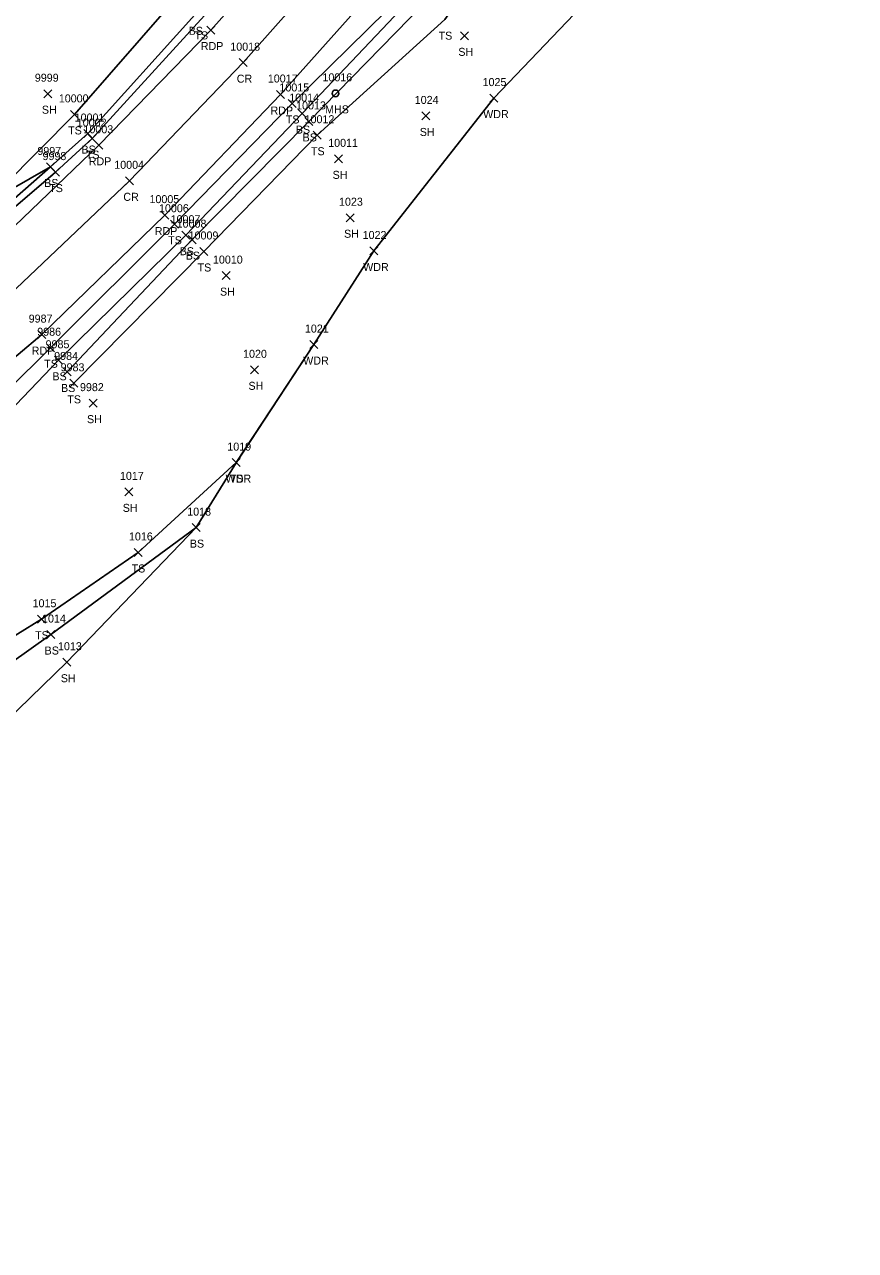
# Model space of a CAD drawing. Extents: x 1651685 to 1653558, y 889533 to 891085.
# Drawn here: x 1652499.4 to 1652707.1, y 889769.1 to 890075.4 of the extents above; entities that cross this region are included whole.
import ezdxf

# ---------------------------------------------------------------- set-up
doc = ezdxf.new("R2010")
doc.units = 0
for name, color, linetype in [('L_A', 7, 'Continuous'), ('L_I', 7, 'Continuous'), ('L_TIC', 7, 'Continuous'), ('LAWA', 7, 'Continuous'), ('LELB', 7, 'Continuous'), ('LSOGP', 7, 'Continuous'), ('P_A', 7, 'Continuous'), ('P_I', 7, 'Continuous'), ('P_TIC', 7, 'Continuous'), ('PET', 7, 'Continuous'), ('PRC', 7, 'Continuous'), ('U_A', 7, 'Continuous'), ('U_I', 7, 'Continuous'), ('USMH', 7, 'Continuous')]:
    doc.layers.add(name, color=color, linetype=linetype)

msp = doc.modelspace()

# ---------------------------------------------------------------- linework, layer by layer
at = {"layer": 'L_TIC'}
for points in [[(1652608.31, 890071.58), (1652610.31, 890073.58)], [(1652610.31, 890071.58), (1652608.31, 890073.58)], [(1652504.25, 890057.12), (1652506.25, 890059.12)], [(1652506.25, 890057.12), (1652504.25, 890059.12)], [(1652615.65, 890056.03), (1652617.65, 890058.03)], [(1652617.65, 890056.03), (1652615.65, 890058.03)], [(1652565.28, 890054.69), (1652567.28, 890056.69)], [(1652567.28, 890054.69), (1652565.28, 890056.69)], [(1652567.75, 890052.15), (1652569.75, 890054.15)], [(1652569.75, 890052.15), (1652567.75, 890054.15)], [(1652510.88, 890051.95), (1652512.88, 890053.95)], [(1652512.88, 890051.95), (1652510.88, 890053.95)], [(1652569.45, 890050.2), (1652571.45, 890052.2)], [(1652571.45, 890050.2), (1652569.45, 890052.2)], [(1652598.68, 890051.57), (1652600.68, 890053.57)], [(1652600.68, 890051.57), (1652598.68, 890053.57)], [(1652514.19, 890047.17), (1652516.19, 890049.17)], [(1652516.19, 890047.17), (1652514.19, 890049.17)], [(1652571.57, 890046.75), (1652573.57, 890048.75)], [(1652573.57, 890046.75), (1652571.57, 890048.75)], [(1652515.29, 890045.9), (1652517.29, 890047.9)], [(1652517.29, 890045.9), (1652515.29, 890047.9)], [(1652576.9, 890040.85), (1652578.9, 890042.85)], [(1652578.9, 890040.85), (1652576.9, 890042.85)], [(1652504.87, 890038.82), (1652506.87, 890040.82)], [(1652506.87, 890038.82), (1652504.87, 890040.82)], [(1652504.87, 890038.82), (1652506.87, 890040.82)], [(1652506.87, 890038.82), (1652504.87, 890040.82)], [(1652506.16, 890037.54), (1652508.16, 890039.54)], [(1652508.16, 890037.54), (1652506.16, 890039.54)], [(1652535.9, 890024.51), (1652537.9, 890026.51)], [(1652537.9, 890024.51), (1652535.9, 890026.51)], [(1652579.76, 890026.14), (1652581.76, 890028.14)], [(1652581.76, 890026.14), (1652579.76, 890028.14)], [(1652538.73, 890021.77), (1652540.73, 890023.77)], [(1652540.73, 890021.77), (1652538.73, 890023.77)], [(1652540.26, 890020.66), (1652542.26, 890022.66)], [(1652542.26, 890020.66), (1652540.26, 890022.66)], [(1652543.24, 890017.71), (1652545.24, 890019.71)], [(1652545.24, 890017.71), (1652543.24, 890019.71)], [(1652585.67, 890017.83), (1652587.67, 890019.83)], [(1652587.67, 890017.83), (1652585.67, 890019.83)], [(1652548.76, 890011.68), (1652550.76, 890013.68)], [(1652550.76, 890011.68), (1652548.76, 890013.68)], [(1652570.67, 889994.45), (1652572.67, 889996.45)], [(1652572.67, 889994.45), (1652570.67, 889996.45)], [(1652504.9, 889993.66), (1652506.9, 889995.66)], [(1652506.9, 889993.66), (1652504.9, 889995.66)], [(1652506.93, 889990.53), (1652508.93, 889992.53)], [(1652508.93, 889990.53), (1652506.93, 889992.53)], [(1652555.88, 889988.15), (1652557.88, 889990.15)], [(1652557.88, 889988.15), (1652555.88, 889990.15)], [(1652509.07, 889987.61), (1652511.07, 889989.61)], [(1652511.07, 889987.61), (1652509.07, 889989.61)], [(1652510.69, 889984.78), (1652512.69, 889986.78)], [(1652512.69, 889984.78), (1652510.69, 889986.78)], [(1652515.52, 889979.82), (1652517.52, 889981.82)], [(1652517.52, 889979.82), (1652515.52, 889981.82)], [(1652551.29, 889964.96), (1652553.29, 889966.96)], [(1652553.29, 889964.96), (1652551.29, 889966.96)], [(1652551.29, 889964.96), (1652553.29, 889966.96)], [(1652553.29, 889964.96), (1652551.29, 889966.96)], [(1652524.46, 889957.66), (1652526.46, 889959.66)], [(1652526.46, 889957.66), (1652524.46, 889959.66)], [(1652541.27, 889948.72), (1652543.27, 889950.72)], [(1652543.27, 889948.72), (1652541.27, 889950.72)], [(1652526.76, 889942.52), (1652528.76, 889944.52)], [(1652528.76, 889942.52), (1652526.76, 889944.52)], [(1652502.63, 889925.84), (1652504.63, 889927.84)], [(1652504.63, 889925.84), (1652502.63, 889927.84)], [(1652504.98, 889922.02), (1652506.98, 889924.02)], [(1652506.98, 889922.02), (1652504.98, 889924.02)], [(1652508.97, 889915.1), (1652510.97, 889917.1)], [(1652510.97, 889915.1), (1652508.97, 889917.1)]]:
    msp.add_lwpolyline(points, dxfattribs=at)
at = {"layer": 'LAWA'}
msp.add_lwpolyline([(1652552.29, 889965.96), (1652571.67, 889995.45), (1652586.67, 890018.83), (1652616.65, 890057.03), (1652642.24, 890083.82), (1652665.45, 890109.51), (1652678.78, 890135.45), (1652680.4, 890163.12)], dxfattribs=at)
at = {"layer": 'LELB'}
for points in [[(1652293.22, 889915.66), (1652303.09, 889907.93), (1652317.35, 889908.79), (1652320.69, 889910.3), (1652331.92, 889916.22), (1652367.25, 889934.93), (1652401.81, 889955.3), (1652430.74, 889974.75), (1652457.46, 889995.31), (1652485.92, 890020.39), (1652507.16, 890038.54), (1652516.29, 890046.9), (1652543.45, 890076.69), (1652569.75, 890105.32), (1652598.99, 890142.55), (1652623.84, 890175.33), (1652642.78, 890202.62), (1652649.43, 890213.08), (1652650.34, 890219.8), (1652662.3, 890235.67), (1652673.05, 890250.91), (1652676.63, 890257.99), (1652674.28, 890264.42)], [(1652348.15, 889927.34), (1652366.56, 889935.99), (1652400.4, 889956.7), (1652430.05, 889976.64), (1652456.7, 889996.32), (1652485.07, 890021.64), (1652505.87, 890039.82), (1652515.19, 890048.17), (1652541.97, 890077.83), (1652568.76, 890106.07), (1652597.37, 890144.26), (1652620.77, 890177.54), (1652638.78, 890206.49), (1652647.21, 890219), (1652658.7, 890237.83), (1652668.92, 890254.32), (1652671.69, 890259.27)], [(1652059.96, 889769.15), (1652077.1, 889776.34), (1652118.69, 889793.55), (1652148.83, 889805.14), (1652195.57, 889824.7), (1652235.22, 889839.02), (1652273.17, 889851.71), (1652312.19, 889868.5), (1652346.46, 889887.35), (1652384.44, 889904.89), (1652418.63, 889927.64), (1652449.26, 889948.79), (1652484.18, 889973.18), (1652505.9, 889994.66), (1652536.9, 890025.51), (1652566.28, 890055.69), (1652594.63, 890083.58), (1652622.18, 890122.04), (1652650.06, 890154.47), (1652669.87, 890181.83), (1652676.09, 890189.41), (1652687.77, 890202.23), (1652700.09, 890224.17)], [(1652442.28, 889988.62), (1652454.4, 889999.19), (1652483.45, 890024.67), (1652494.27, 890035.14), (1652511.88, 890052.95), (1652537.3, 890082.09), (1652561.99, 890110.81), (1652590.74, 890149.47), (1652610.85, 890183.15), (1652631.18, 890211.95), (1652637.71, 890221.97)], [(1652510.07, 889988.61), (1652541.26, 890021.66), (1652570.45, 890051.2), (1652599.26, 890080.66), (1652627.52, 890117.73), (1652652.74, 890152.48), (1652673.77, 890178.69), (1652683.33, 890184.78), (1652690.8, 890198.36), (1652694.16, 890203.39)], [(1652425.64, 889918.85), (1652456.73, 889936.26), (1652476.98, 889952.39), (1652484.78, 889967.5), (1652507.93, 889991.53), (1652539.73, 890022.77), (1652568.75, 890053.15), (1652596.44, 890082.38), (1652624.72, 890120.12), (1652650.78, 890153.9), (1652671.99, 890180.33), (1652678.44, 890186.86), (1652688.88, 890200.58)], [(1652511.69, 889985.78), (1652544.24, 890018.71), (1652572.57, 890047.75), (1652604.47, 890076.62), (1652630.9, 890114.29), (1652657.79, 890149.33), (1652679, 890174.4)], [(1652442.28, 889988.62), (1652455.64, 889997.63), (1652483.78, 890023.8), (1652495.71, 890034.02), (1652505.87, 890039.82)], [(1652398.35, 889877.86), (1652432.84, 889888.72), (1652473.98, 889908.53), (1652503.63, 889926.84), (1652527.76, 889943.52), (1652552.29, 889965.96)], [(1652401.49, 889872.63), (1652432.48, 889885.98), (1652475.79, 889901.66), (1652505.98, 889923.02), (1652542.27, 889949.72)]]:
    msp.add_lwpolyline(points, dxfattribs=at)
at = {"layer": 'LSOGP'}
msp.add_lwpolyline([(1652318.58, 889855.03), (1652374.55, 889845.16), (1652409.98, 889861.38), (1652417.45, 889861.35), (1652444.27, 889869.07), (1652485.55, 889892.44), (1652509.97, 889916.1), (1652542.26, 889949.72), (1652552.29, 889965.95), (1652571.67, 889995.46), (1652586.67, 890018.83), (1652616.64, 890057.03), (1652642.24, 890083.82)], dxfattribs=at)
at = {"layer": 'P_TIC'}
for points in [[(1652544.96, 890073.03), (1652546.96, 890075.03)], [(1652546.96, 890073.03), (1652544.96, 890075.03)], [(1652553.01, 890064.88), (1652555.01, 890066.88)], [(1652555.01, 890064.88), (1652553.01, 890066.88)], [(1652562.38, 890056.92), (1652564.38, 890058.92)], [(1652564.38, 890056.92), (1652562.38, 890058.92)], [(1652516.96, 890044.24), (1652518.96, 890046.24)], [(1652518.96, 890044.24), (1652516.96, 890046.24)], [(1652524.65, 890035.36), (1652526.65, 890037.36)], [(1652526.65, 890035.36), (1652524.65, 890037.36)], [(1652533.46, 890026.79), (1652535.46, 890028.79)], [(1652535.46, 890026.79), (1652533.46, 890028.79)], [(1652502.7, 889996.94), (1652504.7, 889998.94)], [(1652504.7, 889996.94), (1652502.7, 889998.94)]]:
    msp.add_lwpolyline(points, dxfattribs=at)
at = {"layer": 'PET'}
for points in [[(1652310.07, 889873.86), (1652345.02, 889890.88), (1652381.13, 889910.27), (1652416.22, 889931.73), (1652447.25, 889952.29), (1652474.07, 889972.99), (1652503.7, 889997.94), (1652534.46, 890027.79), (1652563.38, 890057.92), (1652590.11, 890087.92), (1652620.33, 890123.88), (1652646.59, 890156.84), (1652667.23, 890184.01), (1652673.84, 890192.76), (1652698.19, 890224.99), (1652707.05, 890238.8), (1652697.14, 890249.86), (1652688.17, 890260.37)], [(1652333.65, 889912.67), (1652369.12, 889931.53), (1652403.15, 889952.41), (1652433.06, 889972.26), (1652459.32, 889992.68), (1652488.38, 890016.94), (1652517.96, 890045.24), (1652545.96, 890074.03), (1652572.08, 890103.38), (1652602.1, 890139.63), (1652627.16, 890172.83), (1652646.68, 890199.42), (1652655.75, 890211.75), (1652675.09, 890240.6), (1652688.17, 890260.37)]]:
    msp.add_lwpolyline(points, dxfattribs=at)
at = {"layer": 'PRC'}
msp.add_lwpolyline([(1652339.13, 889902.36), (1652374.76, 889921.45), (1652409.7, 889942.76), (1652439.67, 889962.96), (1652466.37, 889983.16), (1652495.64, 890007.9), (1652525.65, 890036.36), (1652554.01, 890065.88), (1652580.92, 890096.26), (1652611.45, 890132.24), (1652636.96, 890165.09), (1652656.96, 890191.59), (1652665.11, 890202.52), (1652686.51, 890233.67), (1652697.14, 890249.86)], dxfattribs=at)
at = {"layer": 'USMH'}
for p, q in [((1652577.09, 890058.21), (1652577.09, 890058.21)), ((1652577.92, 890058.21), (1652577.92, 890058.21))]:
    msp.add_line(p, q, dxfattribs=at)
msp.add_circle((1652577.09, 890058.21), 0.833, dxfattribs=at)

# ---------------------------------------------------------------- texts
at = {"layer": 'L_A'}
for s, p in [('BS', (1652540.41, 890072.83)), ('BS', (1652540.41, 890072.83)), ('TS', (1652541.86, 890071.69)), ('TS', (1652602.88, 890071.62)), ('SH', (1652607.8, 890067.58)), ('SH', (1652503.74, 890053.12)), ('TS', (1652564.69, 890050.69)), ('WDR', (1652614.01, 890052.03)), ('TS', (1652510.29, 890047.95)), ('BS', (1652567.19, 890048.15)), ('BS', (1652568.89, 890046.2)), ('SH', (1652598.17, 890047.57)), ('BS', (1652513.63, 890043.17)), ('TS', (1652514.7, 890041.9)), ('TS', (1652570.98, 890042.75)), ('SH', (1652576.39, 890036.85)), ('BS', (1652504.32, 890034.82)), ('BS', (1652504.32, 890034.82)), ('TS', (1652505.57, 890033.54)), ('SH', (1652579.25, 890022.14)), ('TS', (1652535.3, 890020.51)), ('BS', (1652538.17, 890017.77)), ('BS', (1652539.7, 890016.66)), ('TS', (1652542.65, 890013.71)), ('WDR', (1652584.03, 890013.83)), ('SH', (1652548.25, 890007.68)), ('TS', (1652504.31, 889989.66)), ('WDR', (1652569.04, 889990.45)), ('BS', (1652506.37, 889986.53)), ('BS', (1652508.52, 889983.61)), ('SH', (1652555.37, 889984.15)), ('TS', (1652510.1, 889980.78)), ('SH', (1652515.01, 889975.82)), ('WDR', (1652549.65, 889960.96)), ('TS', (1652550.7, 889960.96)), ('SH', (1652523.95, 889953.66)), ('BS', (1652540.71, 889944.72)), ('TS', (1652526.17, 889938.52)), ('TS', (1652502.04, 889921.84)), ('BS', (1652504.42, 889918.02)), ('SH', (1652508.46, 889911.1))]:
    msp.add_text(s, height=2, dxfattribs=at).set_placement(p)
at = {"layer": 'L_I'}
for s, p in [('9999', (1652501.98, 890061.12)), ('10015', (1652563.1, 890058.69)), ('1025', (1652613.87, 890060.03)), ('10000', (1652507.97, 890055.95)), ('10014', (1652565.57, 890056.15)), ('1024', (1652596.91, 890055.57)), ('10013', (1652567.27, 890054.2)), ('10001', (1652511.93, 890051.17)), ('10002', (1652512.46, 890049.9)), ('10012', (1652569.39, 890050.75)), ('10011', (1652575.29, 890044.85)), ('9997', (1652502.61, 890042.82)), ('9997', (1652502.61, 890042.82)), ('9998', (1652503.9, 890041.54)), ('10006', (1652533.01, 890028.51)), ('1023', (1652577.99, 890030.14)), ('10007', (1652535.91, 890025.77)), ('10008', (1652537.43, 890024.66)), ('10009', (1652540.41, 890021.71)), ('1022', (1652583.9, 890021.83)), ('10010', (1652546.49, 890015.68)), ('9986', (1652502.58, 889997.66)), ('1021', (1652569.47, 889998.45)), ('9985', (1652504.67, 889994.53)), ('9984', (1652506.82, 889991.61)), ('1020', (1652554.02, 889992.15)), ('9983', (1652508.43, 889988.78)), ('9982', (1652513.26, 889983.82)), ('1019', (1652550.08, 889968.96)), ('1019', (1652550.08, 889968.96)), ('1017', (1652523.25, 889961.66)), ('1018', (1652540.06, 889952.72)), ('1016', (1652525.5, 889946.52)), ('1015', (1652501.42, 889929.84)), ('1014', (1652503.78, 889926.02)), ('1013', (1652507.77, 889919.1))]:
    msp.add_text(s, height=2, dxfattribs=at).set_placement(p)
at = {"layer": 'P_A'}
for s, p in [('RDP', (1652543.45, 890069.03)), ('CR', (1652552.44, 890060.88)), ('RDP', (1652560.87, 890052.92)), ('RDP', (1652515.45, 890040.24)), ('CR', (1652524.09, 890031.36)), ('RDP', (1652531.95, 890022.79)), ('RDP', (1652501.19, 889992.94))]:
    msp.add_text(s, height=2, dxfattribs=at).set_placement(p)
at = {"layer": 'P_I'}
for s, p in [('10018', (1652550.83, 890068.88)), ('10017', (1652560.2, 890060.92)), ('10003', (1652514.13, 890048.24)), ('10004', (1652521.83, 890039.36)), ('10005', (1652530.63, 890030.79)), ('9987', (1652500.44, 890000.94))]:
    msp.add_text(s, height=2, dxfattribs=at).set_placement(p)
at = {"layer": 'U_A'}
msp.add_text('MHS', height=2, dxfattribs=at).set_placement((1652574.5, 890053.21))
at = {"layer": 'U_I'}
msp.add_text('10016', height=2, dxfattribs=at).set_placement((1652573.85, 890061.21))

doc.saveas('drawing.dxf')
